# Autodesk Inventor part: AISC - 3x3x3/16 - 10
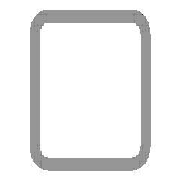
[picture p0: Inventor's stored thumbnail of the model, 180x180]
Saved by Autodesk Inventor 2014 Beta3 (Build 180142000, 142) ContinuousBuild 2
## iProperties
_CCFamilyMember: 9
_CCFamilyDisplayName: ANSI AISC (Square) - Tube
_FrameMemberDoc: Frame Member File
_Version: 15.0.0
_GetPNFromCC: 1
Created: 2011-01
Part Number: AISC - 3x3x3/16 - 10
Material: Steel, Mild
Description: Tube
Document SubType Name: Modeling
Standard: ANSI
Designer: Beta-8540w
Standards Organization: ANSI
Language: en-US
Size Designation: 3x3x3/16
Categories: <MemberInstance><Categories><Category DisplayName="Structural Shapes" InternalName="089c4875-fa83-4c05-b084-43b9cc11f5ed" Mnemonic="GRDR"><CategoryParameter Dis
Stock Number: 3x3x3/16
Density: 7.86 g/cm^3
Appearance: Steel
IsCustomPart: 1
G_L: 10.000 in
G_W: 3.000 in
G_H: 3.000 in
Author: Beta-8540w
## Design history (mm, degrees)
node "Start plane"
node "End plane"
sketch "Sketch"
  geometry: L1 (-38.1, -28.575)-(-38.1, 28.575); L2 (-28.575, 38.1)-(28.575, 38.1); L3 (38.1, 28.575)-(38.1, -28.575); L4 (28.575, -38.1)-(-28.575, -38.1); L5 (-28.575, 33.337)-(28.575, 33.338); L6 (33.338, 28.575)-(33.338, -28.575); L7 (28.575, -33.337)-(-28.575, -33.338); L8 (-33.338, -28.575)-(-33.338, 28.575); L9 (0, 56.102)-(0, -56.102) reference; L10 (-56.102, 0)-(56.102, 0) reference; A1 r 9.525 centre (-28.575, -28.575) between (-38.1, -28.575) and (-28.575, -38.1); A2 r 9.525 centre (-28.575, 28.575) between (-28.575, 38.1) and (-38.1, 28.575); A3 r 9.525 centre (28.575, 28.575) between (38.1, 28.575) and (28.575, 38.1); A4 r 9.525 centre (28.575, -28.575) between (28.575, -38.1) and (38.1, -28.575); A5 r 4.763 centre (-28.575, 28.575) between (-28.575, 33.337) and (-33.338, 28.575); A6 r 4.763 centre (28.575, 28.575) between (33.338, 28.575) and (28.575, 33.338); A7 r 4.763 centre (28.575, -28.575) between (28.575, -33.337) and (33.338, -28.575); A8 r 4.763 centre (-28.575, -28.575) between (-33.338, -28.575) and (-28.575, -33.338)
  constraints: 16 end point, 16 point on circle, 8 centre point, 8 tangent, 4 parallel, 3 equal radius, 2 perpendicular, 7 other
  dimensions: "d10" = 76.2 distance between parallel lines of L2 L4 (= G_H); "d11" = 76.2 distance between parallel lines of L1 L3 (= G_W); "d12" = 4.7625 distance between parallel lines of L3 L6 (= G_T); "d15" = 38.1 distance between parallel lines of L2 L10 (= 0.5 x d10); "d16" = 38.1 distance between parallel lines of L9 L3 (= 0.5 x d11); "d17" = 9.525 radius of A1 (= G_IR)
extrude "Body" new body sketch "Sketch" stored distance "d3" = 254 (= G_L); taper "d4" = 0 deg
node "Driven Length"
  sketch "Sketch3"
    geometry: L1 (0, 0)-(10, 0) reference
    constraints: 2 end point, 1 horizontal
  workplane "Work Plane3"
  sketch "Sketch4"
    geometry: L1 (-2, 0)-(12, 0) reference; L2 (-2, 254)-(12, 254) reference
    dimensions: "d19" = 254 distance between parallel lines of L1 L2 (derived)
body "Solid1"
other parameters: "G_W" = 76.2 [user parameter; used in 1 equation term], "G_H" = 76.2 [user parameter; used in 1 equation term], "G_T" = 4.7625 [user parameter; used in 1 equation term], "G_IR" = 9.525 [user parameter; used in 1 equation term], "G_L" = 254 (= d19) [user parameter; used in 1 equation term], "G_OFFSET_START" = 0 [user parameter; used in 1 equation term], "G_OFFSET_END" = 0 [user parameter; used in 1 equation term], "d13" = 0 (computed from G_OFFSET_START), "d14" = 254 (= G_OFFSET_END + B_L), "B_L" = 254 [user parameter; used in 1 equation term], "d18" = 90 deg
